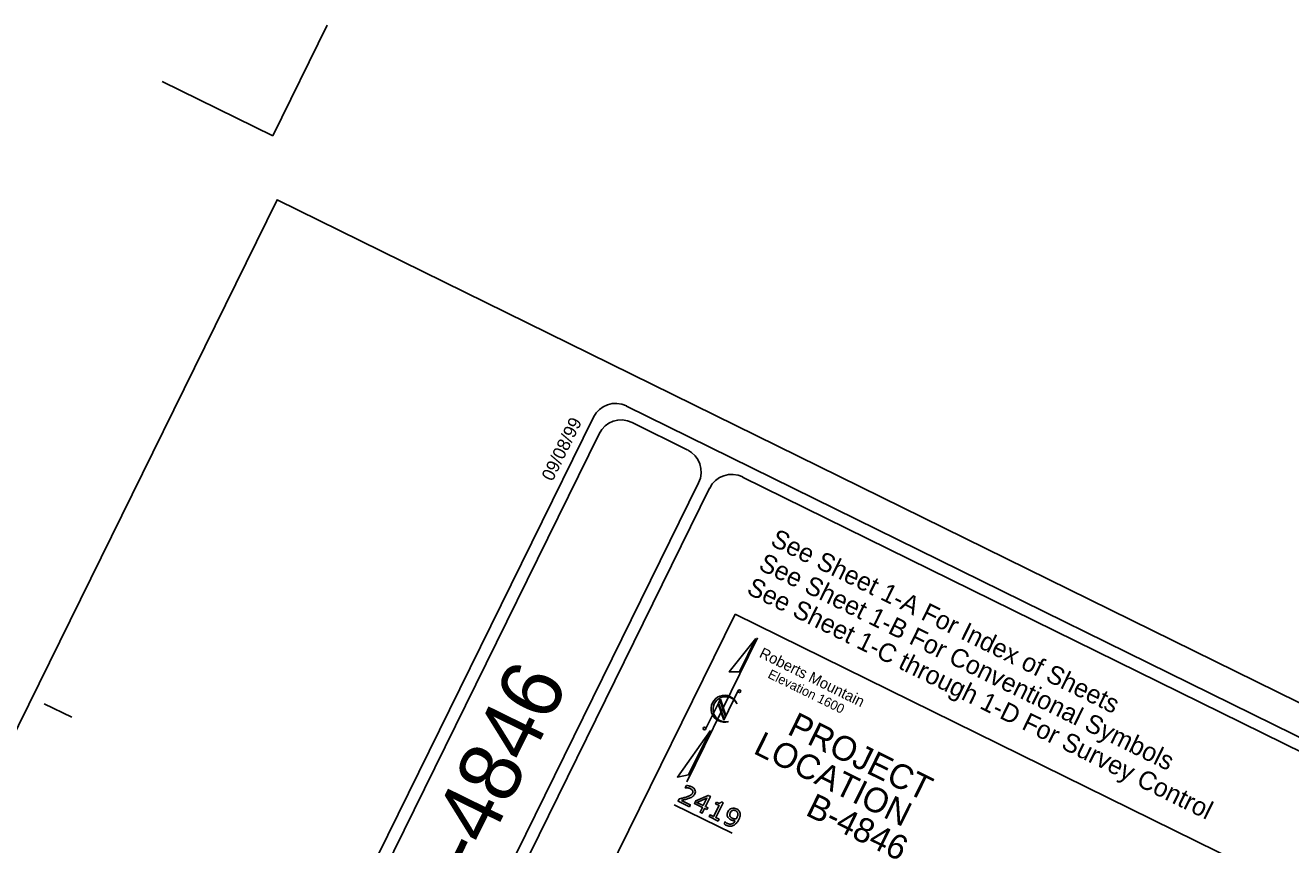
# Model space of a CAD drawing. Extents: x 1428128 to 1430390, y 857947 to 859822.
# Drawn here: x 1428792 to 1429306, y 859435 to 859768 of the extents above; entities that cross this region are included whole.
import ezdxf

# ---------------------------------------------------------------- set-up
doc = ezdxf.new("R2010")
doc.units = 0
for name, color, linetype in [('Exist Horizontal Alignment Station Label', 7, 'Continuous'), ('Old_Level_1', 7, 'Continuous'), ('Sheet North Arrow CELL', 7, 'Continuous'), ('Sheet Plot Border Inside CELL', 7, 'Continuous'), ('Sheet Title CELL', 7, 'Continuous')]:
    doc.layers.add(name, color=color, linetype=linetype)

msp = doc.modelspace()

# ---------------------------------------------------------------- linework, layer by layer
at = {"layer": 'Exist Horizontal Alignment Station Label'}
for q in [(1428914.9, 859767.6), (1428847.96, 859744.81)]:
    msp.add_line((1428892.82, 859722.74), q, dxfattribs=at)
at = {"layer": 'Old_Level_1'}
msp.add_line((1429055.56, 859451.51), (1429079.02, 859439.97), dxfattribs=at)
for points in [[(1429060.08, 859458.35), (1429060.04, 859458.37), (1429060.5, 859459.32)], [(1429061.72, 859450.71), (1429057.16, 859452.95), (1429057.63, 859453.9)], [(1429068.87, 859449.54), (1429067.87, 859450.04), (1429066.94, 859448.14), (1429066.07, 859448.57), (1429067.01, 859450.46), (1429063.78, 859452.05), (1429064.29, 859453.09), (1429069.42, 859455.28), (1429070.25, 859454.87), (1429068.23, 859450.76), (1429069.23, 859450.27), (1429068.87, 859449.54)], [(1429067.36, 859451.19), (1429068.86, 859454.23), (1429064.75, 859452.47), (1429067.36, 859451.19)], [(1429058.48, 859453.27), (1429062.11, 859451.49), (1429061.72, 859450.71)], [(1429073.47, 859444.93), (1429069.82, 859446.72), (1429070.16, 859447.41), (1429071.56, 859446.72), (1429073.78, 859451.23), (1429072.38, 859451.92), (1429072.68, 859452.53)], [(1429074.71, 859452.7), (1429075.41, 859452.36), (1429072.43, 859446.29), (1429073.8, 859445.62), (1429073.47, 859444.93)], [(1429075.78, 859443.76), (1429076.21, 859444.63), (1429076.25, 859444.6)]]:
    msp.add_lwpolyline(points, dxfattribs=at)
for points in [[(1429060.5, 859459.32), (1429060.9, 859459.32), (1429061.5, 859459.19), (1429062.1, 859459.06), (1429062.61, 859458.81), (1429063.64, 859458.3), (1429063.99, 859457.51), (1429064.33, 859456.72), (1429063.91, 859455.87), (1429063.72, 859455.49), (1429063.46, 859455.2), (1429063.2, 859454.92), (1429062.86, 859454.71), (1429062.55, 859454.52), (1429062.18, 859454.37), (1429061.81, 859454.21), (1429061.31, 859454.05), (1429060.59, 859453.81), (1429059.85, 859453.62), (1429059.12, 859453.43), (1429058.48, 859453.27)], [(1429057.63, 859453.9), (1429058.31, 859454.08), (1429058.99, 859454.25), (1429059.66, 859454.42), (1429060.27, 859454.62), (1429061.56, 859455.03), (1429062.12, 859455.37), (1429062.69, 859455.7), (1429062.97, 859456.28), (1429063.23, 859456.8), (1429063.03, 859457.27), (1429062.83, 859457.73), (1429062.2, 859458.04), (1429061.79, 859458.24), (1429061.24, 859458.33), (1429060.69, 859458.43), (1429060.08, 859458.35)], [(1429072.68, 859452.53), (1429072.97, 859452.39), (1429073.32, 859452.28), (1429073.67, 859452.17), (1429073.88, 859452.18), (1429074.14, 859452.19), (1429074.35, 859452.3), (1429074.55, 859452.42), (1429074.71, 859452.7)], [(1429076.25, 859444.6), (1429076.35, 859444.47), (1429076.56, 859444.29), (1429076.77, 859444.11), (1429077.06, 859443.97), (1429078.06, 859443.48), (1429078.92, 859443.8), (1429079.78, 859444.12), (1429080.39, 859445.12), (1429079.84, 859445.08), (1429079.42, 859445.15), (1429079, 859445.22), (1429078.56, 859445.44), (1429078.14, 859445.64), (1429077.85, 859445.89), (1429077.55, 859446.14), (1429077.33, 859446.54), (1429077.07, 859447.01), (1429077.08, 859447.54), (1429077.08, 859448.06), (1429077.38, 859448.65), (1429077.88, 859449.68), (1429078.88, 859450), (1429079.88, 859450.31), (1429080.85, 859449.83), (1429081.34, 859449.59), (1429081.68, 859449.24), (1429082.02, 859448.88), (1429082.19, 859448.42), (1429082.38, 859447.86), (1429082.3, 859447.17), (1429082.22, 859446.47), (1429081.76, 859445.54)], [(1429080.94, 859446.19), (1429081.28, 859446.89), (1429081.35, 859447.38), (1429081.41, 859447.88), (1429081.28, 859448.24), (1429081.16, 859448.55), (1429080.96, 859448.75), (1429080.76, 859448.96), (1429080.48, 859449.1), (1429079.83, 859449.42), (1429079.25, 859449.2), (1429078.68, 859448.98), (1429078.31, 859448.24), (1429078.1, 859447.81), (1429078.09, 859447.48), (1429078.08, 859447.15), (1429078.27, 859446.8), (1429078.4, 859446.56), (1429078.62, 859446.4), (1429078.84, 859446.23), (1429079.14, 859446.08), (1429079.49, 859445.91), (1429079.9, 859445.83), (1429080.31, 859445.74), (1429080.71, 859445.77), (1429080.76, 859445.86), (1429080.81, 859445.95), (1429080.87, 859446.04), (1429080.94, 859446.19)], [(1429081.76, 859445.54), (1429081.32, 859444.65), (1429080.77, 859444.03), (1429080.21, 859443.41), (1429079.56, 859443.11), (1429078.89, 859442.79), (1429078.14, 859442.82), (1429077.38, 859442.84), (1429076.54, 859443.25), (1429076.31, 859443.37), (1429076.11, 859443.5), (1429075.92, 859443.62), (1429075.78, 859443.76)]]:
    msp.add_open_spline(points, degree=3, dxfattribs=at)
at = {"layer": 'Sheet North Arrow CELL'}
for p, q in [((1429060.64, 859460.87), (1429089.33, 859519.19)), ((1429081.54, 859497.81), (1429075.66, 859485.84)), ((1429074.31, 859494.36), (1429068.32, 859482.19)), ((1429075.66, 859485.84), (1429073.39, 859492.5)), ((1429074.09, 859493.92), (1429073.55, 859492.83)), ((1429075.82, 859486.17), (1429073.55, 859492.83)), ((1429073.55, 859492.83), (1429075.82, 859486.17)), ((1429076.36, 859487.27), (1429074.09, 859493.92)), ((1429076.57, 859487.71), (1429074.31, 859494.36)), ((1429081, 859492.54), (1429081.04, 859492.46)), ((1429075.82, 859486.17), (1429076.36, 859487.27))]:
    msp.add_line(p, q, dxfattribs=at)
for points in [[(1429088.68, 859518.88), (1429077.9, 859505.37), (1429082.06, 859505.42)], [(1429070.27, 859481.65), (1429056.86, 859462.73), (1429061.44, 859463.7)]]:
    msp.add_lwpolyline(points, close=True, dxfattribs=at)
for centre in [(1429082.02, 859497.57), (1429067.84, 859482.41)]:
    msp.add_circle(centre, 0.53, dxfattribs=at)
for centre, radius, start, end in [((1429075.96, 859490.45), 5.46, 21.6401, 286.1942), ((1429076.44, 859490.22), 5.12, 26.8952, 282.4288)]:
    msp.add_arc(centre, radius, start, end, dxfattribs=at)
at = {"layer": 'Sheet Plot Border Inside CELL'}
msp.add_lwpolyline([(1428428.74, 858750.16), (1429924.03, 858014.39), (1430389.86, 858961.09), (1428894.57, 859696.85)], close=True, dxfattribs=at)
at = {"layer": 'Sheet Title CELL'}
for p, q in [((1428623.95, 858684.82), (1429065.46, 859582.08)), ((1428710.12, 858848.61), (1429069.94, 859579.87)), ((1428939, 859241.66), (1429080.28, 859528.78)), ((1429080.28, 859528.78), (1429358.43, 859391.92)), ((1428800.15, 859492.5), (1428811.36, 859486.98)), ((1428800.15, 859492.5), (1428811.36, 859486.98))]:
    msp.add_line(p, q, dxfattribs=at)
for points in [[(1430364.14, 858959.76), (1429036.18, 859613.2)], [(1429022.8, 859608.64), (1428576.88, 858702.41)], [(1429022.8, 859608.64), (1428576.88, 858702.41)], [(1429060.89, 859595.46), (1429038.47, 859606.5)], [(1429025.09, 859601.94), (1428583.58, 858704.69)], [(1430357.43, 858957.48), (1429083.34, 859584.41)]]:
    msp.add_lwpolyline(points, dxfattribs=at)
for centre, start, end in [((1429031.8, 859604.26), 63.8001, 153.8001), ((1429034.08, 859597.57), 63.8001, 153.8001), ((1429056.51, 859586.53), 333.8001, 63.8001), ((1429078.94, 859575.5), 63.8001, 153.8001)]:
    msp.add_arc(centre, 10, start, end, dxfattribs=at)

# ---------------------------------------------------------------- texts
at = {"layer": 'Old_Level_1'}
for s, height, p in [('Roberts Mountain', 4.4, (1429089.71, 859511.53)), ('Elevation 1600', 3.8, (1429093.22, 859503.19)), ('PROJECT', 10, (1429101, 859480.39)), ('LOCATION', 10, (1429087.19, 859472.57)), ('B-4846', 10, (1429108.37, 859447.54))]:
    msp.add_text(s, height=height, rotation=333.8001, dxfattribs=at).set_placement(p)
at = {"layer": 'Sheet Title CELL'}
for s, height, rotation, p in [('09/08/99', 5.25, 63.8001, (1429006.25, 859582.37)), ('See Sheet 1-A For Index of Sheets', 7.5, 333.8001, (1429094.14, 859556.95)), ('See Sheet 1-B For Conventional Symbols', 7.5, 333.8001, (1429089.31, 859547.14)), ('See Sheet 1-C through 1-D For Survey Control', 7.5, 333.8001, (1429084.49, 859537.34)), ('B-4846', 25, 63.8001, (1428965.2, 859404.11))]:
    msp.add_text(s, height=height, rotation=rotation, dxfattribs=at).set_placement(p)

doc.saveas('drawing.dxf')
